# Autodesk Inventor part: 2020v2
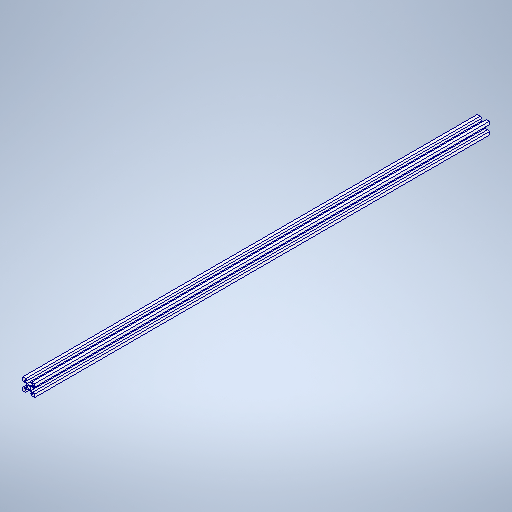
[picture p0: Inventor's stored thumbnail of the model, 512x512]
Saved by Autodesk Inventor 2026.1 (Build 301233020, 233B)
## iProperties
Created: 2024-09
Part Number: 2020v2
Material: Alluminio 6061
Document SubType Name: Modeling
Designer: hp
Density: 2.7 g/cm^3
Appearance: Default
Author: hp
Revision Number: ANY
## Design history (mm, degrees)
node "Solido1"
sketch "Sketch3"
  geometry: 2 further points
hole "Hole3" sketch "Sketch3" at (32.222, -3.027), (16.972, -3.027) diameter "d14" = 4.5; stored, may be unused: countersink angle "d18" = 90 deg, drill point angle "d20" = 0 deg; dims "d15" = 6, "d16" = 4, "d17" = 2, "d19" = 8
sketch "Sketch8"
  geometry: 2 further points
hole "Hole8" sketch "Sketch8" at (742, 3.053), (755, 3.053) diameter "d49" = 4.5; stored, may be unused: countersink angle "d53" = 90 deg, drill point angle "d55" = 0 deg; dims "d50" = 6, "d51" = 4, "d52" = 2, "d54" = 8
sketch "Sketch9"
  geometry: 2 further points
hole "Hole9" sketch "Sketch9" at (690.765, -3.027), (714.765, -3.027) diameter "d56" = 3.4; stored, may be unused: countersink angle "d60" = 90 deg, drill point angle "d62" = 0 deg; dims "d57" = 6, "d58" = 4, "d59" = 2, "d61" = 8
sketch "Sketch10"
  geometry: 1 further point
hole "Hole10" sketch "Sketch10" at (82.6, -3.277) diameter "d63" = 4.5; stored, may be unused: countersink angle "d67" = 90 deg, drill point angle "d69" = 0 deg; dims "d64" = 6, "d65" = 4, "d66" = 2, "d68" = 8
sketch "Sketch11"
  geometry: 1 further point
hole "Hole11" sketch "Sketch11" at (42.9, -3.277) diameter "d70" = 4.5; stored, may be unused: countersink angle "d74" = 90 deg, drill point angle "d76" = 0 deg; dims "d71" = 6, "d72" = 4, "d73" = 2, "d75" = 8
sketch "Sketch12"
  geometry: 2 further points
hole "Hole12" sketch "Sketch12" at (673.778, -3.027), (657.778, -3.027) diameter "d77" = 3.4; stored, may be unused: countersink angle "d81" = 90 deg, drill point angle "d83" = 0 deg; dims "d78" = 6, "d79" = 4, "d80" = 2, "d82" = 8
body "Solid1"
